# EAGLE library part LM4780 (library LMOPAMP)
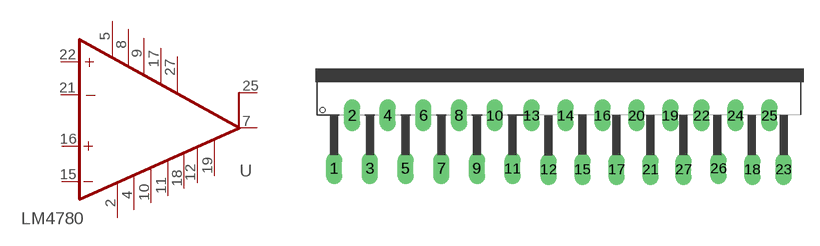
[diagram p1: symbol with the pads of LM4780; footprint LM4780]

Designator prefix -

## LM4780  [LM4780]
2  V-  pwr
4  V-1  pwr
5  V+  pwr
7  OUT  out
8  V+1  pwr
9  V+2  pwr
10  V-2  pwr
11  V-3  pwr
12  V-5  pwr
15  -INA  in
16  +INA  in
17  V+3  pwr
18  V-4  pwr
19  V-6  pwr
21  -INB  in
22  +INB  in
25  OUT1  out
27  V+4  pwr

## Footprint LM4780 (pad centres in mm)
drill 1.016 long: 1 -7.239,1.905; 2 -5.537,6.96; 3 -3.835,1.905; 4 -2.134,6.96; 5 -0.432,1.905; 6 1.27,6.96; 7 2.972,1.905; 8 4.674,6.96; 9 6.375,1.905; 10 8.077,6.96; 11 9.779,1.905; 12 13.207,1.83; 13 11.587,6.96; 14 14.827,6.96; 15 16.447,1.83; 16 18.337,6.96; 17 19.687,1.83; 18 32.647,1.83; 19 24.817,6.96; 20 21.577,6.96; 21 22.927,1.83; 22 27.787,6.96; 23 35.617,1.83; 24 31.027,6.96; 25 34.267,6.96; 26 29.407,1.93; 27 26.067,1.83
